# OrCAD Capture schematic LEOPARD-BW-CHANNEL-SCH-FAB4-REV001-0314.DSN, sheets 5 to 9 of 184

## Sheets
5 174_P1V26_STBY_TPS74801: size A4; title: P1V26_STBY_TPS74801
6 173_P1V538_STBY_TPS74801: size Custom; title: P1V538_STBY_TPS74801
7 172_P1V8_STBY_TPS53312: size A3; title: P11V8_STBY_TPS53312
8 171_P1V5_PCH_TPS74801: size Custom; title: P1V5_PCH_TPS74801
9 170_P1V05_STBY_PCH_TPS53511: size A3; title: P1V05_STBY_PCH_TPS53511

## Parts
sheet 170_P1V05_STBY_PCH_TPS53511
PC772  SC1U16V3KX-5GP  [C603H36]
PC773  SCD1U16V2KX-3GP  [C402H22]
PC774  SC10U16V5KX-1-GP  [C805H54]
PC775  SC10U16V5KX-1-GP  [C805H54]
PC776  SCD1U50V3KX-GP  [C603H36]
PC777  SC3300P50V2KX-1GP  [C402H22]
PC778  SC1U16V3KX-5GP  [C603H36]
PC779  SCD1U50V3KX-GP  [C603H36]
PC780  SC22U6D3V5MX-5-GP  [C805H56]
PC781  SC22U6D3V5MX-5-GP  [C805H56]
PC782  SC22U6D3V5MX-5-GP  [C805H56]
PC783  SC1KP50V2KX-1GP  [C402H22]
PC1058  SC1KP50V2KX-1GP  [C402H22]
PC1059  SC2K2P50V3KX-GP  [C603]
PC1060  SC1U10V2KX-4-GP  [C402H22]
PD3  PTZ2D4-GP  [D502715AKH87]
PG49  GAP-CLOSE-PWR-4-GP  [GAP-CLOSE-PWR-4]
PG50  COPPER-CLOSE-GP-U  [CON2C-U]
PL40  IND-4D7UH-185-GP-U  [L6965-1632-UH119]
PR449  2D2R3-1-U-GP  [R603H22]
PR450  0R6J-3-GP  [R1206H28]
PR451  10KR2F-2-GP  [R402H16]
PR452  3K74R2F-GP  [R402H16]
PR453  10R3F-GP  [R603H22]
PR454  0R2J-2-GP  [R402H16]
PR455  6K65R2F-GP  [R402H16]
PR456  2KR2F-3-GP  [R402H16]
PR457  10KR2F-2-GP  [R402H16]
PR458  10KR2F-2-GP  [R402H16]
PR459  0R2J-2-GP  [R402H16]
PR809  0R2J-2-GP  [R402H16]
PR810  3D01R5F-GP  [R805H24]
PU39  TPS53511RGTR-GP  [QFN16G3-G1D7H40]
sheet 171_P1V5_PCH_TPS74801
PC786  SCD1U16V2KX-3GP  [C402H22]
PC915  SC10U16V6KX-2GP  [C1206H71]
PC922  SC470P50V2KX-3GP  [C402H22]
PC923  SC10U16V6KX-2GP  [C1206H71]
PC924  SCD1U16V2KX-3GP  [C402H22]
PC925  SCD1U16V2KX-3GP  [C402H22]
PC926  SC10U6D3V5KX-4GP  [C805H58]
PC927  SC10U6D3V5KX-4GP  [C805H58]
PC928  SC10U6D3V5KX-4GP  [C805H58]
PC929  SC10U6D3V5KX-4GP  [C805H58]
PC930  SCD1U16V2KX-3GP  [C402H22]
PC1068  SC1KP50V2JN-2GP  [C402H22]
PR175  4K75R2F-1-GP  [R402H16]
PR187  0R6J-3-GP  [R1206H28]
PR205  0R2J-2-GP  [R402H16]
PR206  0R6J-3-GP  [R1206H28]
PR226  10KR2F-2-GP  [R402H16]
PR227  4K12R2F-GP  [R402H16]
PR462  10KR2F-2-GP  [R402H16]
PR465  0R3J-0-U-GP  [R603H22]
PU43  TPS74801RGW-GP  [QFN20-1G3D15H40]
sheet 172_P1V8_STBY_TPS53312
PC796  SC1KP50V2KX-1GP  [C402H22]
PC797  SC10U16V5KX-1-GP  [C805H54]
PC798  SC22U6D3V5MX-5-GP  [C805H56]
PC799  SC1U16V3KX-5GP  [C603H36]
PC800  SC22U6D3V5MX-5-GP  [C805H56]
PC801  SCD1U50V3KX-GP  [C603H36]
PC802  SCD1U16V2KX-3GP  [C402H22]
PC803  SC22U6D3V5MX-5-GP  [C805H56]
PC804  SC3300P50V2KX-1GP  [C402H22]
PC805  SCD1U50V3KX-GP  [C603H36]
PC806  SC1U16V3KX-5GP  [C603H36]
PC807  SC10U16V5KX-1-GP  [C805H54]
PC910  SCD1U16V3KX-3GP  [C603H36]
PC1061  SC1U10V2KX-4-GP  [C402H22]
PC1062  SC2K2P50V3KX-GP  [C603]
PC1063  SC1KP50V2KX-1GP  [C402H22]
PD4  PTZ2D4-GP  [D502715AKH87]
PG51  GAP-CLOSE-PWR-4-GP  [GAP-CLOSE-PWR-4]
PG52  COPPER-CLOSE-GP-U  [CON2C-U]
PL54  IND-3D3UH-131-GP  [L4947-1015H119]
PR467  6K65R2F-GP  [R402H16]
PR468  10KR2F-2-GP  [R402H16]
PR470  10KR2F-2-GP  [R402H16]
PR471  0R2J-2-GP  [R402H16]
PR472  0R6J-3-GP  [R1206H28]
PR473  0R2J-2-GP  [R402H16]
PR474  2D2R3-1-U-GP  [R603H22]
PR475  10R3F-GP  [R603H22]
PR476  13K3R2F-L1-GP  [R402H16]
PR477  2KR2F-3-GP  [R402H16]
PR811  0R2J-2-GP  [R402H16]
PR812  3D01R5F-GP  [R805H24]
PU41  TPS53312RGTR-GP  [QFN16G3-G1D7H40]
sheet 173_P1V538_STBY_TPS74801
PC784  SCD1U16V2KX-3GP  [C402H22]
PC785  SC2700P50V2KX-1-GP  [C402H22]
PC787  SC10U16V6KX-2GP  [C1206H71]
PC788  SC10U16V6KX-2GP  [C1206H71]
PC789  SCD1U16V2KX-3GP  [C402H22]
PC810  SCD1U16V2KX-3GP  [C402H22]
PC811  SC10U6D3V5KX-4GP  [C805H58]
PC812  SC10U6D3V5KX-4GP  [C805H58]
PC813  SC10U6D3V5KX-4GP  [C805H58]
PC814  SC10U6D3V5KX-4GP  [C805H58]
PC815  SCD1U16V2KX-3GP  [C402H22]
PR65  10KR2F-2-GP  [R402H16]
PR69  3K3R2D-GP  [R402H16]
PR88  3K16R2F-GP  [R402H16]
PR89  0R6J-3-GP  [R1206H28]
PR106  0R2J-2-GP  [R402H16]
PR112  0R6J-3-GP  [R1206H28]
PR118  0R2J-2-GP  [R402H16]
PR478  0R2J-2-GP  [R402H16]
PR718  4K75R2F-1-GP  [R402H16]
PU40  TPS74801RGW-GP  [QFN20-1G3D15H40]
sheet 174_P1V26_STBY_TPS74801
PC893  SCD1U16V2KX-3GP  [C402H22]
PC894  SC10U16V6KX-2GP  [C1206H71]
PC895  SC10U6D3V5KX-4GP  [C805H58]
PC896  SC470P50V2KX-3GP  [C402H22]
PC897  SCD1U16V2KX-3GP  [C402H22]
PC898  SCD1U16V2KX-3GP  [C402H22]
PC899  SC10U6D3V5KX-4GP  [C805H58]
PC900  SC10U6D3V5KX-4GP  [C805H58]
PC901  SC10U16V6KX-2GP  [C1206H71]
PC902  SC10U6D3V5KX-4GP  [C805H58]
PC903  SCD1U16V2KX-3GP  [C402H22]
PR7  2K74R2F-GP  [R402H16]
PR130  0R6J-3-GP  [R1206H28]
PR132  0R2J-2-GP  [R402H16]
PR152  4K32R2F-GP  [R402H16]
PR153  0R2J-2-GP  [R402H16]
PR154  10KR2F-2-GP  [R402H16]
PR155  0R6J-3-GP  [R1206H28]
PR720  4K75R2F-1-GP  [R402H16]
PU42  TPS74801RGW-GP  [QFN20-1G3D15H40]

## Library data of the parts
PC772 PC778 PC799 PC806 = SC1U16V3KX-5GP: CHIP CAP C 1U 16V K0603 X7R; GREENDFACTOR: R2_SA;HF_SA;G_SA;; MAIN_SOURCE: M; Package Type: SMD-BCG3; Part Number: 78.10521.2BL; SPEC: http://wpqssvr.wistron.com.tw:7001/wpqs/servlet/COM.qpart.Attachment?PartNumber=78.10521.2BL
PC773 PC802 = SCD1U16V2KX-3GP: CHIP CAP C 0.1U 16V K0402 X7R; GREENDFACTOR: R2_SA;HF_SA;G_SA;; MAIN_SOURCE: M; Package Type: SMD-BCG; Part Number: 78.10421.2FL; SPEC: http://wpqssvr.wistron.com.tw:7001/wpqs/servlet/COM.qpart.Attachment?PartNumber=78.10421.2FL
PC774 PC775 PC797 PC807 = SC10U16V5KX-1-GP: CHIP CAP C 10U 16V K0805 X6S; GREENDFACTOR: R2_SA;; Package Type: SMD-BCG5; Part Number: 78.10621.81L; SPEC: http://wpqssvr.wistron.com.tw:7001/wpqs/servlet/COM.qpart.Attachment?PartNumber=78.10621.81L
PC776 PC801 = SCD1U50V3KX-GP: CHIP CAP C 0.1U 50V K0603 X7R; GREENDFACTOR: R2_SA;HF_SA;G_SA;; Level: SMD; MAIN_SOURCE: M; Package Type: RCL_GP; Part Number: 78.10424.2BL; Part Type: RCL_GP; SPEC: http://wpqssvr.wistron.com.tw:7001/wpqs/servlet/COM.qpart.Attachment?PartNumber=78.10424.2BL; Status: POP
PC777 PC804 = SC3300P50V2KX-1GP: CHIP CAP C 3300P 50V K0402 X7R; GREENDFACTOR: R2_SA;HF_SA;G_SA;; MAIN_SOURCE: M; Package Type: SMD-BCG; Part Number: 78.33224.2FL; SPEC: http://wpqssvr.wistron.com.tw:7001/wpqs/servlet/COM.qpart.Attachment?PartNumber=78.33224.2FL
PC779 PC805 = SCD1U50V3KX-GP: CHIP CAP C 0.1U 50V K0603 X7R; GREENDFACTOR: R2_SA;HF_SA;G_SA;; Level: SMD; MAIN_SOURCE: M; POP?: NOPOP; Package Type: RCL_GP; Part Number: 78.10424.2BL; Part Type: RCL_GP; SPEC: http://wpqssvr.wistron.com.tw:7001/wpqs/servlet/COM.qpart.Attachment?PartNumber=78.10424.2BL
PC780-PC782 PC798 PC800 PC803 = SC22U6D3V5MX-5-GP: CHIP CAP C 22U 6.3V M0805 X6S; GREENDFACTOR: R2_SA;HF_SA;G_SA;; Package Type: SMD-BCG2; Part Number: 78.22610.81L; SPEC: http://wpqssvr.wistron.com.tw:7001/wpqs/servlet/COM.qpart.Attachment?PartNumber=78.22610.81L
PC783 PC796 = SC1KP50V2KX-1GP: CHIP CAP 1000P50V K0402 X7R(RO; GREENDFACTOR: R2_SA;HF_SA;G_SA;; Level: SMD; MAIN_SOURCE: M; POP?: NOPOP; Package Type: SMD-BCG; Part Number: 78.10224.2FL; Part Type: SMD-BCG; SPEC: http://wpqssvr.wistron.com.tw:7001/wpqs/servlet/COM.qpart.Attachment?PartNumber=78.10224.2FL
PC1058 PC1063 = SC1KP50V2KX-1GP: CHIP CAP C 1000P 50V K0402 X7R; CATEGORIES: CAP_Small; GREENDFACTOR: R2_SA;HF_SA;G_SA;; MAIN_SOURCE: M; Part Number: 78.10224.2FL; Part Type: SMD-BCG; SPEC: http://wpqssvr.wistron.com.tw:7001/wpqs/servlet/COM.qpart.Attachment?PartNumber=78.10224.2FL
PC1059 PC1062 = SC2K2P50V3KX-GP: CHIP CAP C 2200P 50V K0603 X7R; GREENDFACTOR: R2_SA;HF_SA;G_SA;; Level: SMD; POP?: NOPOP; Package Type: SMD-BCG6; Part Number: 78.22224.2BL; Part Type: SMD-BCG6; SPEC: http://wpqssvr.wistron.com.tw:7001/wpqs/servlet/COM.qpart.Attachment?PartNumber=78.22224.2BL; Status: POP
PC1060 PC1061 = SC1U10V2KX-4-GP: CHIP CAP C 1U 10V K 0402 X6S; GREENDFACTOR: R2_SA;HF_SA;; POP?: NOPOP; Package Type: SMD-BCG6; Part Number: 78.10523.8FL; SPEC: http://wpqssvr.wistron.com.tw:7001/wpqs/servlet/COM.qpart.Attachment?PartNumber=78.10523.8FL
PD3 PD4 = PTZ2D4-GP: DIODE ZEN PTZ2.4B 2.4V PMDS; GREENDFACTOR: R2_SA;; Package Type: DISCRET-G7; Part Number: 83.2R403.F3H; SPEC: http://wpqssvr.wistron.com.tw:7001/wpqs/servlet/COM.qpart.Attachment?PartNumber=83.2R403.F3H
PG49 PG51 = GAP-CLOSE-PWR-4-GP: PAD FOR COPPER-CLOSE; GREENDFACTOR: R2_C;; Package Type: DISCRET-G7; Part Number: ZZ.C0N2C.011; SPEC: http://wpqssvr.wistron.com.tw:7001/wpqs/servlet/COM.qpart.Attachment?PartNumber=ZZ.C0N2C.011
PG50 PG52 = COPPER-CLOSE-GP-U: COPPER CLOSE; GREENDFACTOR: Regular;; Level: SMD; Package Type: DISCRET-G9; Part Number: ZZ.CON2C.XXX; Part Type: DISCRET-G9; SPEC: http://wpqssvr.wistron.com.tw:7001/wpqs/servlet/COM.qpart.Attachment?PartNumber=ZZ.CON2C.XXX
PL40 = IND-4D7UH-185-GP-U: CHIP IND 4.7UH SPM6530T-4R7M; Alternate: 68.4R710.20R; GREENDFACTOR: R2_SA;HF_SA;; Level: SMD; Package Type: DISCRET-G9; Part Number: 68.4R71C.10U; SPEC: http://wpqssvr.wistron.com.tw:7001/wpqs/servlet/COM.qpart.Attachment?PartNumber=68.4R71C.10U; Status: POP
PR449 PR474 = 2D2R3-1-U-GP: CHIP RES 2.2 F 1/10W 0603(ROHS; GREENDFACTOR: R2_SA;HF_SA;G_SA;; Package Type: RCL_GP; Part Number: 64.2R205.55L; SPEC: http://wpqssvr.wistron.com.tw:7001/wpqs/servlet/COM.qpart.Attachment?PartNumber=64.2R205.55L
PR450 PR472 = 0R6J-3-GP: CHIP RES 0 J 1/4W 1206 (ROHS); GREENDFACTOR: R2_SA;HF_SA;G_SA;; Level: SMD; Package Type: SMD-RG; Part Number: 63.R0032.11L; Part Type: SMD-RG; SPEC: http://wpqssvr.wistron.com.tw:7001/wpqs/servlet/COM.qpart.Attachment?PartNumber=63.R0032.11L; Status: POP
PR451 PR457 PR470 = 10KR2F-2-GP: CHIP RES 10K F 1/16W 0402; GREENDFACTOR: R2_SA;HF_SA;G_SA;; Level: SMD; Package Type: SMD-RG; Part Number: 64.10025.6DL; Part Type: SMD-RG; SPEC: http://wpqssvr.wistron.com.tw:7001/wpqs/servlet/COM.qpart.Attachment?PartNumber=64.10025.6DL; Status: POP
PR452 = 3K74R2F-GP: CHIP RES 3.74K F 1/16W 0402; GREENDFACTOR: R2_SA;HF_SA;G_SA;; Package Type: RCL_GP; Part Number: 64.37415.6DL; SPEC: http://wpqssvr.wistron.com.tw:7001/wpqs/servlet/COM.qpart.Attachment?PartNumber=64.37415.6DL
PR453 PR475 = 10R3F-GP: CHIP RES 10 F 1/10W 0603; GREENDFACTOR: R2_SA;HF_SA;G_SA;; Level: SMD; Package Type: RCL_GP; Part Number: 64.10R05.55L; Part Type: RCL_GP; SPEC: http://wpqssvr.wistron.com.tw:7001/wpqs/servlet/COM.qpart.Attachment?PartNumber=64.10R05.55L; Status: POP
PR454 PR459 PR471 PR473 PR478 PR809 PR811 = 0R2J-2-GP: CHIP RES 0 J 1/16W 0402; GREENDFACTOR: R2_SA;HF_SA;G_SA;; Level: SMD; Package Type: SMD-RG; Part Number: 63.R0034.1DL; Part Type: SMD-RG; ROOM: VR_CHIPSET; SPEC: http://wpqssvr.wistron.com.tw:7001/wpqs/servlet/COM.qpart.Attachment?PartNumber=63.R0034.1DL; Status: POP
PR455 PR467 = 6K65R2F-GP: CHIP RES 6.65K F 1/16W 0402; GREENDFACTOR: R2_SA;HF_SA;G_SA;; Package Type: RCL_GP; Part Number: 64.66515.6DL; SPEC: http://wpqssvr.wistron.com.tw:7001/wpqs/servlet/COM.qpart.Attachment?PartNumber=64.66515.6DL
PR456 PR477 = 2KR2F-3-GP: CHIP RES 2K F 1/16W 0402; GREENDFACTOR: R2_SA;HF_SA;G_SA;; POP?: NOPOP; Package Type: SMD-RG; Part Number: 64.20015.6DL; SPEC: http://wpqssvr.wistron.com.tw:7001/wpqs/servlet/COM.qpart.Attachment?PartNumber=64.20015.6DL
PR458 PR462 = 10KR2F-2-GP: CHIP RES 10K F 1/16W 0402; GREENDFACTOR: R2_SA;HF_SA;G_SA;; Level: SMD; POP?: NOPOP; Package Type: SMD-RG; Part Number: 64.10025.6DL; Part Type: SMD-RG; SPEC: http://wpqssvr.wistron.com.tw:7001/wpqs/servlet/COM.qpart.Attachment?PartNumber=64.10025.6DL
PR810 PR812 = 3D01R5F-GP: CHIP RES 3.01 F 1/8W 0805; GREENDFACTOR: R2_SA;HF_SA;G_SA;; Level: SMD; POP?: NOPOP; Package Type: SMD-RG5; Part Number: 64.3R015.16L; Part Type: SMD-RG5; SPEC: http://wpqssvr.wistron.com.tw:7001/wpqs/servlet/COM.qpart.Attachment?PartNumber=64.3R015.16L; Status: POP
PU39 = TPS53511RGTR-GP: IC PWM CTRL TPS53511RGTR QFN 16P; GREENDFACTOR: R2_SA;; Part Number: 74.53511.073; Part Type: DISCRET-G9; SPEC: http://wpqssvr.wistron.com.tw:7001/wpqs/servlet/COM.qpart.Attachment?PartNumber=74.53511.073
PC786 = SCD1U16V2KX-3GP: CHIP CAP C 0.1U 16V K0402 X7R; GREENDFACTOR: R2_SA;HF_SA;G_SA;; MAIN_SOURCE: M; POP?: NOPOP; Package Type: SMD-BCG; Part Number: 78.10421.2FL; SPEC: http://wpqssvr.wistron.com.tw:7001/wpqs/servlet/COM.qpart.Attachment?PartNumber=78.10421.2FL
PC787 PC788 PC894 PC901 PC915 PC923 = SC10U16V6KX-2GP: CHIP CAP C 10U 16V K1206 X7R; GREENDFACTOR: R2_SA;HF_SA;G_SA;; Package Type: SMD-BCG; Part Number: 78.10621.22L; Part Type: SMD-BCG; SPEC: http://wpqssvr.wistron.com.tw:7001/wpqs/servlet/COM.qpart.Attachment?PartNumber=78.10621.22L
PC896 PC922 = SC470P50V2KX-3GP: CHIP CAP 470P50V K0402 X7R(ROH; CATEGORIES: CAP_Small; GREENDFACTOR: R2_SA;HF_SA;G_SA;; MAIN_SOURCE: M; Package Type: SMD-BCG; Part Number: 78.47124.2FL; Part Type: SMD-BCG; SPEC: http://wpqssvr.wistron.com.tw:7001/wpqs/servlet/COM.qpart.Attachment?PartNumber=78.47124.2FL
PC789 PC898 PC924 = SCD1U16V2KX-3GP: CHIP CAP C 0.1U 16V K0402 X7R; CATEGORIES: CAP_1.xV; GREENDFACTOR: R2_SA;HF_SA;G_SA;; MAIN_SOURCE: M; Package Type: SMD-BCG; Part Number: 78.10421.2FL; SPEC: http://wpqssvr.wistron.com.tw:7001/wpqs/servlet/COM.qpart.Attachment?PartNumber=78.10421.2FL
PC810 PC893 PC925 = SCD1U16V2KX-3GP: CHIP CAP C 0.1U 16V K0402 X7R; CATEGORIES: CAP_1.xV; GREENDFACTOR: R2_SA;HF_SA;G_SA;; MAIN_SOURCE: M; Package Type: SMD-BCG; Part Number: 78.10421.2FL; Part Type: SMD-BCG; SPEC: http://wpqssvr.wistron.com.tw:7001/wpqs/servlet/COM.qpart.Attachment?PartNumber=78.10421.2FL
PC811 PC814 PC899 PC900 PC926 PC929 = SC10U6D3V5KX-4GP: CHIP CAP C 10U 6.3V K0805 X7R; GREENDFACTOR: R2_SA;HF_SA;G_SA;; Package Type: SMD-BCG; Part Number: 78.10620.21L; Part Type: SMD-BCG; SPEC: http://wpqssvr.wistron.com.tw:7001/wpqs/servlet/COM.qpart.Attachment?PartNumber=78.10620.21L
PC812 PC813 PC895 PC902 PC927 PC928 = SC10U6D3V5KX-4GP: CHIP CAP C 10U 6.3V K0805 X7R; GREENDFACTOR: R2_SA;HF_SA;G_SA;; Package Type: SMD-BCG; Part Number: 78.10620.21L; SPEC: http://wpqssvr.wistron.com.tw:7001/wpqs/servlet/COM.qpart.Attachment?PartNumber=78.10620.21L
PC815 PC897 PC930 = SCD1U16V2KX-3GP: CHIP CAP C 0.1U 16V K0402 X7R; 0.1uF: 0.1uF; 0402: 0402; 16V: 16V; CATEGORIES: CAP_1.xV; Category: PWRSW_VCCL; GREENDFACTOR: R2_SA;HF_SA;G_SA;; MAIN_SOURCE: M; Module: POWER_OTHER; Part Number: 78.10421.2FL; Part Type: SMD-BCG; ROOM: VR_7V; SPEC: http://wpqssvr.wistron.com.tw:7001/wpqs/servlet/COM.qpart.Attachment?PartNumber=78.10421.2FL; X7R: X7R
PC1068 = SC1KP50V2JN-2GP: CHIP CAP C 1000P 50V J0402 NPO; GREENDFACTOR: R2_SA;HF_SA;G_SA;; Package Type: SMD-BCG; Part Number: 78.10234.1FL; SPEC: http://wpqssvr.wistron.com.tw:7001/wpqs/servlet/COM.qpart.Attachment?PartNumber=78.10234.1FL
PR175 = 4K75R2F-1-GP: CHIP RES 4.75K F 1/16W 0402; GREENDFACTOR: R2_SA;HF_SA;G_SA;; Package Type: RCL_GP; Part Number: 64.47515.6DL; Part Type: RCL_GP; SPEC: http://wpqssvr.wistron.com.tw:7001/wpqs/servlet/COM.qpart.Attachment?PartNumber=64.47515.6DL
PR89 PR112 PR130 PR155 PR187 PR206 = 0R6J-3-GP: CHIP RES 0 J 1/4W 1206 (ROHS); GREENDFACTOR: R2_SA;HF_SA;G_SA;; Package Type: SMD-RG; Part Number: 63.R0032.11L; Part Type: SMD-RG; SPEC: http://wpqssvr.wistron.com.tw:7001/wpqs/servlet/COM.qpart.Attachment?PartNumber=63.R0032.11L
PR106 PR153 PR205 = 0R2J-2-GP: CHIP RES 0 J 1/16W 0402; GREENDFACTOR: R2_SA;HF_SA;G_SA;; Package Type: SMD-RG; Part Number: 63.R0034.1DL; Part Type: SMD-RG; SPEC: http://wpqssvr.wistron.com.tw:7001/wpqs/servlet/COM.qpart.Attachment?PartNumber=63.R0034.1DL
PR65 PR154 PR226 PR468 = 10KR2F-2-GP: CHIP RES 10K F 1/16W 0402; GREENDFACTOR: R2_SA;HF_SA;G_SA;; Level: SMD; Package Type: SMD-RG; Part Number: 64.10025.6DL; Part Type: SMD-RG; SPEC: http://wpqssvr.wistron.com.tw:7001/wpqs/servlet/COM.qpart.Attachment?PartNumber=64.10025.6DL
PR227 = 4K12R2F-GP: CHIP RES 4.12K F 1/16W 0402; GREENDFACTOR: R2_SA;HF_SA;G_SA;; Part Number: 64.41215.6DL; Part Type: RCL_GP; SPEC: http://wpqssvr.wistron.com.tw:7001/wpqs/servlet/COM.qpart.Attachment?PartNumber=64.41215.6DL
PR465 = 0R3J-0-U-GP: CHIP RES 0 J 1/10W 0603; GREENDFACTOR: R2_SA;HF_SA;G_SA;; Level: SMD; Part Number: 63.00000.00L; Part Type: RCL_GP; Status: POP
PU40 PU42 PU43 = TPS74801RGW-GP: IC LDO TPS74801RGW QFN 20P; GREENDFACTOR: R2_SA;; Package Type: DISCRET-G3; Part Number: 74.74801.A33; Part Type: DISCRET-G3; SPEC: http://wpqssvr.wistron.com.tw:7001/wpqs/servlet/COM.qpart.Attachment?PartNumber=74.74801.A33
PC910 = SCD1U16V3KX-3GP: CHIP CAP 0.1U16V K0603 X7R(ROH; GREENDFACTOR: R2_SA;R_SA;HF_SA;G_SA;; Module: VR_SYSTEM_P1V8; Package Type: SMD-BCG; Part Number: 78.10421.2BL; SPEC: http://wpqssvr.wistron.com.tw:7001/wpqs/servlet/COM.qpart.Attachment?PartNumber=78.10421.2BL; Size: 0603; Type: X7R
PL54 = IND-3D3UH-131-GP: CHIP CHOKE 3.3U PCMB053T-3R3MS; GREENDFACTOR: R_SA;; Part Number: 68.3R310.20F; Part Type: DISCRET-G7; SPEC: http://wpqssvr.wistron.com.tw:7001/wpqs/servlet/COM.qpart.Attachment?PartNumber=68.3R310.20F
PR476 = 13K3R2F-L1-GP: CHIP RES 13.3K F 1/16W 0402; GREENDFACTOR: R2_SA;HF_SA;G_SA;; Part Number: 64.13325.6DL; Part Type: SMD-RG; SPEC: http://wpqssvr.wistron.com.tw:7001/wpqs/servlet/COM.qpart.Attachment?PartNumber=64.13325.6DL
PU41 = TPS53312RGTR-GP: IC PWM CTRL TPS53312RGTR QFN 16P; GREENDFACTOR: R2_SA;; Package Type: DISCRET-G4; Part Number: 74.53312.073; SPEC: http://wpqssvr.wistron.com.tw:7001/wpqs/servlet/COM.qpart.Attachment?PartNumber=74.53312.073
PC784 PC903 = SCD1U16V2KX-3GP: CHIP CAP C 0.1U 16V K0402 X7R; CATEGORIES: CAP_1.xV; GREENDFACTOR: R2_SA;HF_SA;G_SA;; MAIN_SOURCE: M; POP?: NOPOP; Package Type: SMD-BCG; Part Number: 78.10421.2FL; Part Type: SMD-BCG; SPEC: http://wpqssvr.wistron.com.tw:7001/wpqs/servlet/COM.qpart.Attachment?PartNumber=78.10421.2FL
PC785 = SC2700P50V2KX-1-GP: CHIP CAP C 2700P 50V K0402 X7R; GREENDFACTOR: R2_SA;HF_SA;G_SA;; Package Type: SMD-BCG1; Part Number: 78.27224.2FL; SPEC: http://wpqssvr.wistron.com.tw:7001/wpqs/servlet/COM.qpart.Attachment?PartNumber=78.27224.2FL
PR69 = 3K3R2D-GP: CHIP RES 3.3K D 1/16W 0402; GREENDFACTOR: R2_SA;HF_SA;G_SA;; Package Type: SMD-RG4; Part Number: 64.33016.6DL; SPEC: http://wpqssvr.wistron.com.tw:7001/wpqs/servlet/COM.qpart.Attachment?PartNumber=64.33016.6DL
PR88 = 3K16R2F-GP: CHIP RES 3.16K F 1/16W 0402; GREENDFACTOR: R2_SA;HF_SA;G_SA;; Part Number: 64.31615.6DL; Part Type: SMD-RG; SPEC: http://wpqssvr.wistron.com.tw:7001/wpqs/servlet/COM.qpart.Attachment?PartNumber=64.31615.6DL
PR118 PR132 = 0R2J-2-GP: CHIP RES 0 J 1/16W 0402; GREENDFACTOR: R2_SA;HF_SA;G_SA;; Part Number: 63.R0034.1DL; Part Type: SMD-RG; SPEC: http://wpqssvr.wistron.com.tw:7001/wpqs/servlet/COM.qpart.Attachment?PartNumber=63.R0034.1DL
PR718 PR720 = 4K75R2F-1-GP: CHIP RES 4.75K F 1/16W 0402; GREENDFACTOR: R2_SA;HF_SA;G_SA;; POP?: NOPOP; Part Number: 64.47515.6DL; Part Type: RCL_GP; SPEC: http://wpqssvr.wistron.com.tw:7001/wpqs/servlet/COM.qpart.Attachment?PartNumber=64.47515.6DL
PR7 = 2K74R2F-GP: CHIP RES 2.74K F 1/16W 0402; GREENDFACTOR: R2_SA;HF_SA;G_SA;; Part Number: 64.27415.6DL; Part Type: RCL_GP; SPEC: http://wpqssvr.wistron.com.tw:7001/wpqs/servlet/COM.qpart.Attachment?PartNumber=64.27415.6DL
PR152 = 4K32R2F-GP: CHIP RES 4.32K F 1/16W 0402; GREENDFACTOR: R2_SA;HF_SA;G_SA;; Part Number: 64.43215.6DL; Part Type: RCL_GP; SPEC: http://wpqssvr.wistron.com.tw:7001/wpqs/servlet/COM.qpart.Attachment?PartNumber=64.43215.6DL

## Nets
AGND_P1V05_STBY_PCH: PC777.2 PG50.1 PR451.1 PU39.4(GND)
AGND_P1V8_STBY_BMC: PC804.2 PG52.1 PR470.1 PU41.4(GND)
GND: PC772.2 PC773.2 PC774.2 PC775.2 PC778.2 PC780.2 PC781.2 PC782.2 PC784.2 PC785.1 PC786.2 PC787.2 PC788.2 PC789.2 PC797.2 PC798.2 PC799.2 PC800.2 PC802.2 PC803.2 PC806.2 PC807.2 PC810.2 PC811.2 PC812.2 PC813.2 PC814.2 PC815.2 PC893.2 PC894.2 PC895.2 PC896.1 PC897.2 PC898.2 PC899.2 PC900.2 PC901.2 PC902.2 PC903.2 PC910.2 PC915.2 PC922.1 PC923.2 PC924.2 PC925.2 PC926.2 PC927.2 PC928.2 PC929.2 PC930.2 PC1060.1 PC1061.1 PC1068.2 PD3.A(ANODE) PD4.A(ANODE) PG50.2 PG52.2 PR88.2 PR152.2 PR175.2 PR457.1 PR468.1 PR810.2 PR812.2 PU39.7(PGND) PU39.8(PGND) PU39.17(GND) PU40.2(NC#2) PU40.3(NC#3) PU40.4(NC#4) PU40.12(GND) PU40.13(NC#13) PU40.14(NC#14) PU40.17(NC#17) PU40.21(GND) PU41.7(PGND) PU41.8(PGND) PU41.17(GND) PU42.2(NC#2) PU42.3(NC#3) PU42.4(NC#4) PU42.12(GND) PU42.13(NC#13) PU42.14(NC#14) PU42.17(NC#17) PU42.21(GND) PU43.2(NC#2) PU43.3(NC#3) PU43.4(NC#4) PU43.12(GND) PU43.13(NC#13) PU43.14(NC#14) PU43.17(NC#17) PU43.21(GND) ; also on sheet 1 2 3 4 10 11 12 13 14 15 16 17 18 19 20 21 22 23 24 25 26 27 28 29 30 31 32 33 34 35 36 37 38 39 44 46 47 49 50 51 52 53 54 55 56 57 58 59 60 61 62 63 64 65 66 69 70 71 73 74 75 76 78 79 80 81 82 83 84 86 87 88 89 90 91 92 93 94 95 96 97 98 99 100 101 102 103 104 105 106 107 108 109 110 111 112 113 114 115 116 117 118 119 128 129 138 139 159 160 161 166 168 169 170 171 172 173 174 175 176 177 180 181 182 183 184
P1V5_PCH: PR206.1 ; also on sheet 45 87 91 166 173
P1V05_STBY_PCH: PC779.2 PC780.1 PC781.1 PC782.1 PD3.K(CATHODE) PG49.1 PL40.2 ; also on sheet 45 76 87
P1V05_STBY_PCH__SNB: PC1059.2 PR810.1
P1V05_STBY_PCH_CC: PG49.2 PR453.1
P1V05_STBY_PCH_CC_R: PC1058.1 PR452.1 PR453.2 PR454.2
P1V05_STBY_PCH_EN_R: PC1060.2 PR458.2 PR459.1 PU39.6(EN)
P1V05_STBY_PCH_SS: PC777.1 PU39.3(SS)
P1V05_STBY_PCH_SW: PC776.1 PC1059.1 PL40.1 PR456.1 PU39.9(SW#9) PU39.10(SW#10) PU39.11(SW#11)
P1V05_STBY_PCH_VBST: PR809.2 PU39.12(VBST)
P1V05_STBY_PCH_VBST_RR: PC776.2 PR809.1
P1V05_STBY_PCH_VCC: PC772.1 PR449.1 PU39.15(VCC)
P1V05_STBY_PCH_VFB: PC783.2 PC1058.2 PR451.2 PR452.2 PU39.1(VFB)
P1V05_STBY_PCH_VFB_R: PC779.1 PC783.1 PR456.2
P1V05_STBY_PCH_VIN: PC773.1 PC774.1 PC775.1 PR450.1 PU39.13(VIN#13) PU39.14(VIN#14)
P1V05_STBY_PCH_VO: PR454.1 PU39.16(VO)
P1V05_STBY_PCH_VRG5: PC778.1 PR455.2 PU39.2(VREG5)
P1V8_STBY: PC798.1 PC800.1 PC803.1 PC805.2 PC910.1 PD4.K(CATHODE) PG51.1 PL54.2(S) PR89.1 PR130.1 PR187.1 ; also on sheet 76
P1V8_STBY_BMC__SNB: PC1062.2 PR812.1
P1V8_STBY_BMC_CC: PG51.2 PR475.1
P1V8_STBY_BMC_CC_R: PC1063.1 PR471.2 PR475.2 PR476.1
P1V8_STBY_BMC_EN_R: PC1061.2 PR473.1 PU41.6(EN)
P1V8_STBY_BMC_SS: PC804.1 PU41.3(SS)
P1V8_STBY_BMC_SW: PC801.1 PC1062.1 PL54.1(F) PR477.1 PU41.9(SW#9) PU41.10(SW#10) PU41.11(SW#11)
P1V8_STBY_BMC_VBST: PR811.2 PU41.12(VBST)
P1V8_STBY_BMC_VBST_RR: PC801.2 PR811.1
P1V8_STBY_BMC_VCC: PC799.1 PR474.1 PU41.15(VCC)
P1V8_STBY_BMC_VFB: PC796.2 PC1063.2 PR470.2 PR476.2 PU41.1(VFB)
P1V8_STBY_BMC_VFB_R: PC796.1 PC805.1 PR477.2
P1V8_STBY_BMC_VIN: PC797.1 PC802.1 PC807.1 PR472.1 PU41.13(VIN#13) PU41.14(VIN#14)
P1V8_STBY_BMC_VO: PR471.1 PU41.16(VO)
P1V8_STBY_BMC_VRG5: PC806.1 PR467.2 PU41.2(VREG5)
P1V26_STBY: PR155.1 ; also on sheet 73
P1V538_STBY: PR112.1 ; also on sheet 73 74
P3V3: PR462.1 ; also on sheet 1 3 45 46 48 49 52 54 58 65 74 76 78 83 84 87 90 91 94 95 96 100 101 102 161 166 168 173 174 177 180 181 182 183
P3V3_STBY: PR65.2 PR154.2 PR226.2 PR458.1 PR718.1 PR720.1 ; also on sheet 2 3 10 11 12 15 16 17 20 21 22 25 26 27 30 31 33 34 35 37 38 39 45 47 49 50 51 52 54 55 59 60 61 62 63 64 65 66 69 70 71 72 73 74 76 79 83 84 87 88 89 90 91 92 93 94 95 96 97 98 99 159 161 166 168 173 174 176 177 179 180 182 183 184
P5V_STBY: PR106.1 PR153.1 PR205.1 ; also on sheet 4 14 15 19 20 24 25 29 30 33 34 37 38 59 61 65 69 76 95
P12V_STBY: PR449.2 PR450.2 PR472.2 PR474.2 ; also on sheet 2 3 4 10 11 12 13 17 18 22 23 27 28 32 36 59 60 75 95 104 105 106 107 108 109 110 111 112 113 114 115 116 117 118 119
FM_SLPA_N: PR459.2 ; also on sheet 90
PWRGD_P1V5_PCH: PC786.1 PR226.1 PU43.9(PG) ; also on sheet 11 51
PWRGD_P1V05_STBY_PCH_P1V0_STBY: PR455.1 PR457.2 PU39.5(PG) ; also on sheet 51
PWRGD_P1V8_STBY: PR118.1 PR467.1 PR468.2 PU41.5(PG)
PWRGD_P1V26_STBY: PR154.1 PU42.9(PG)
PWRGD_P1V538_STBY: PR132.1 PR478.1
PWRGD_P1V538_STBY_R: PR65.1 PR478.2 PU40.9(PG)
PWRGD_P3V3: PR465.1 ; also on sheet 3 51
PWRGD_P3V3_AUX: PR473.2 ; also on sheet 2 55
TPS74801_1V26_BIAS: PC893.1 PR153.2 PU42.10(BIAS)
TPS74801_1V26_EN: PC903.1 PR132.2 PR720.2 PU42.11(EN)
TPS74801_1V26_FB: PR7.2 PR152.1 PU42.16(FB)
TPS74801_1V26_OUT: PC895.1 PC898.1 PC899.1 PC900.1 PC902.1 PR7.1 PR155.2 PU42.1(OUT#1) PU42.18(OUT#18) PU42.19(OUT#19) PU42.20(OUT#20)
TPS74801_1V26_SS: PC896.2 PU42.15(SS)
TPS74801_1V538_BIAS: PC810.1 PR106.2 PU40.10(BIAS)
TPS74801_1V538_EN: PC784.1 PR118.2 PR718.2 PU40.11(EN)
TPS74801_1V538_FB: PR69.2 PR88.1 PU40.16(FB)
TPS74801_1V538_SS: PC785.2 PU40.15(SS)
TPS74801_P1V5_PCH_BIAS: PC925.1 PR205.2 PU43.10(BIAS)
TPS74801_P1V5_PCH_EN: PC1068.1 PR462.2 PR465.2 PU43.11(EN)
TPS74801_P1V5_PCH_FB: PR175.1 PR227.2 PU43.16(FB)
TPS74801_P1V5_PCH_IN: PC915.1 PC923.1 PC930.1 PR187.2 PU43.5(IN#5) PU43.6(IN#6) PU43.7(IN#7) PU43.8(IN#8)
TPS74801_P1V5_PCH_OUT: PC924.1 PC926.1 PC927.1 PC928.1 PC929.1 PR206.2 PR227.1 PU43.1(OUT#1) PU43.18(OUT#18) PU43.19(OUT#19) PU43.20(OUT#20)
TPS74801_P1V5_PCH_SS: PC922.2 PU43.15(SS)
TPS74801_P1V26_IN: PC894.1 PC897.1 PC901.1 PR130.2 PU42.5(IN#5) PU42.6(IN#6) PU42.7(IN#7) PU42.8(IN#8)
TPS74801_P1V538_IN: PC787.1 PC788.1 PC815.1 PR89.2 PU40.5(IN#5) PU40.6(IN#6) PU40.7(IN#7) PU40.8(IN#8)
TPS74801_P1V538_OUT: PC789.1 PC811.1 PC812.1 PC813.1 PC814.1 PR69.1 PR112.2 PU40.1(OUT#1) PU40.18(OUT#18) PU40.19(OUT#19) PU40.20(OUT#20)

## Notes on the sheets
sheet 5
- Power rail :P1V26_STBY(1.26V)
  Controller :TPS74801
  TDC :0.7A
  Max :0.76A
  OCP:2A
- Vout=0.8x(1+Ru/Rd)
  =1.261V
- TSS=VRef x Css/ Iss
  =0.8V*470pF/0.44uA=0.86mS
sheet 6
- Power rail :P1V538_STBY(1.538V)
  Controller :TPS74801
  TDC :0.4A
  Max :0.5A
  OCP:2A
- Vout=0.8x(1+Ru/Rd)
  =1.544V
- FAB1 REV010 20150331
- TSS=VRef x Css/ Iss
  =0.8V*2700pF/0.44uA=4.909mS
sheet 7
- Power rail : P1V8_STBY
  Controller : TPS53312(Fswitching=700KHz)
  TDC : 1.45A
  MAX : 1.96A
  OCP : 4.1A
- Input-Cap RMS Current = 0.69A
- Vout=0.765x(1+Ru/Rd)
  =1.813V
- FAB1 REV010 20150331
- change to 1000pF to improve body plot
  Aston 2015/3/31
- CYNTEC PCMB053T-3R3MS
  L=3.3uH, DCR=32m ohm,
  Idc1=5.0A, Idc2=7.0A
  5.0*5.0*3.0 mm3
- FAB1 REV010 20150331
- FS=700KHz
- SS=1.4ms
sheet 8
- Power rail : P1V5_PCH
  Controller : TPS74801
  TDC : 0.15A
  MAX : 0.2A
  OCP : 2.0A
- Vout=0.8x(1+Ru/Rd)
  =1.494V
- TSS=VRef x Css/ Iss
  =0.8V*470pF/0.44uA=0.86mS
- P1V5_WBG_TPS74801
sheet 9
- Power rail : P1V05_STBY_PCH
  Controller : TPS53511 (Fswitching=700KHz)
  TDC :0.6A
  MAX :0.7A
  OCP :2.05A
- Input-Cap RMS Current = 0.19A
- Vout=0.765x(1+Ru/Rd)
  =1.0511
- FAB1 REV010 20150331
- change to 1000pF to improve body plot
  Aston 2015/3/31
- TDK SPM6530T-4R7M
  L=4.7uH, DCR=35.8m ohm,
  Idc1=6.2A, Idc2=5.6A
  7.1*6.5*3 mm3
- FAB1 REV010 20150331
- FS=700KHz
- SS=1.4ms
- OD pin
- FAB1 20150126
